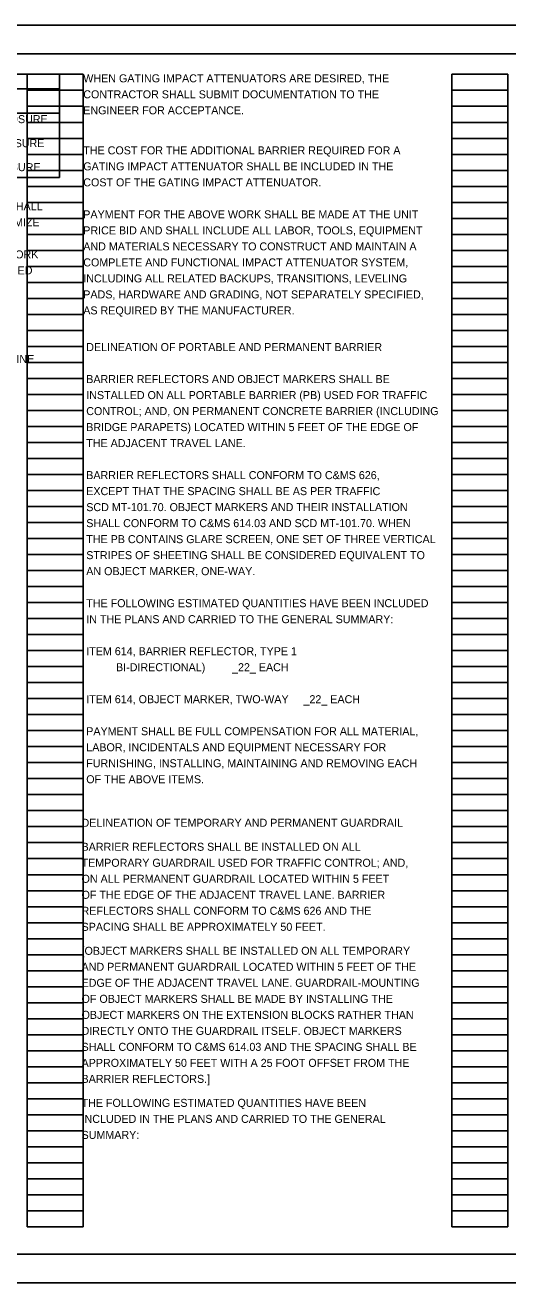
# Model space of a CAD drawing. Extents: x -59 to 65, y -13 to 46.
# Drawn here: x 16.22 to 24.66, y 0 to 22 of the extents above; entities that cross this region are included whole.
import ezdxf

# ---------------------------------------------------------------- set-up
doc = ezdxf.new("R2010")
doc.units = 0
for name, color, linetype in [('SH_Border', 7, 'Continuous'), ('SH_Cut_Line', 7, 'Continuous'), ('SH_Data', 7, 'Continuous'), ('SH_Text', 7, 'Continuous')]:
    doc.layers.add(name, color=color, linetype=linetype)

msp = doc.modelspace()

# ---------------------------------------------------------------- linework, layer by layer
at = {"layer": 'SH_Border'}
msp.add_lwpolyline([(1.5, 21.5), (33.5, 21.5), (33.5, 0.5), (1.5, 0.5)], close=True, dxfattribs=at)
at = {"layer": 'SH_Cut_Line'}
msp.add_lwpolyline([(0, 0), (34, 0), (34, 22), (0, 22)], close=True, dxfattribs=at)
at = {"layer": 'SH_Data'}
for p, q in [((16.26, 0.98), (16.26, 21.14)), ((16.26, 21.14), (17.24, 21.14)), ((17.24, 0.98), (17.24, 21.14)), ((23.68, 0.98), (23.68, 21.14)), ((23.68, 21.14), (24.66, 21.14)), ((24.66, 0.98), (24.66, 21.14)), ((16.26, 20.86), (17.24, 20.86)), ((23.68, 20.86), (24.66, 20.86)), ((16.26, 20.58), (17.24, 20.58)), ((23.68, 20.58), (24.66, 20.58)), ((16.26, 20.3), (17.24, 20.3)), ((23.68, 20.3), (24.66, 20.3)), ((16.26, 20.02), (17.24, 20.02)), ((23.68, 20.02), (24.66, 20.02)), ((16.26, 19.74), (17.24, 19.74)), ((23.68, 19.74), (24.66, 19.74)), ((16.26, 19.46), (17.24, 19.46)), ((23.68, 19.46), (24.66, 19.46)), ((16.26, 19.18), (17.24, 19.18)), ((23.68, 19.18), (24.66, 19.18)), ((16.26, 18.9), (17.24, 18.9)), ((23.68, 18.9), (24.66, 18.9)), ((16.26, 18.62), (17.24, 18.62)), ((23.68, 18.62), (24.66, 18.62)), ((16.26, 18.34), (17.24, 18.34)), ((23.68, 18.34), (24.66, 18.34)), ((16.26, 18.06), (17.24, 18.06)), ((23.68, 18.06), (24.66, 18.06)), ((16.26, 17.78), (17.24, 17.78)), ((23.68, 17.78), (24.66, 17.78)), ((16.26, 17.5), (17.24, 17.5)), ((23.68, 17.5), (24.66, 17.5)), ((16.26, 17.22), (17.24, 17.22)), ((23.68, 17.22), (24.66, 17.22)), ((16.26, 16.94), (17.24, 16.94)), ((23.68, 16.94), (24.66, 16.94)), ((16.26, 16.66), (17.24, 16.66)), ((23.68, 16.66), (24.66, 16.66)), ((16.26, 16.38), (17.24, 16.38)), ((23.68, 16.38), (24.66, 16.38)), ((16.26, 16.1), (17.24, 16.1)), ((23.68, 16.1), (24.66, 16.1)), ((16.26, 15.82), (17.24, 15.82)), ((23.68, 15.82), (24.66, 15.82)), ((16.26, 15.54), (17.24, 15.54)), ((23.68, 15.54), (24.66, 15.54)), ((16.26, 15.26), (17.24, 15.26)), ((23.68, 15.26), (24.66, 15.26)), ((16.26, 14.98), (17.24, 14.98)), ((23.68, 14.98), (24.66, 14.98)), ((16.26, 14.7), (17.24, 14.7)), ((23.68, 14.7), (24.66, 14.7)), ((16.26, 14.42), (17.24, 14.42)), ((23.68, 14.42), (24.66, 14.42)), ((16.26, 14.14), (17.24, 14.14)), ((23.68, 14.14), (24.66, 14.14)), ((16.26, 13.86), (17.24, 13.86)), ((23.68, 13.86), (24.66, 13.86)), ((16.26, 13.58), (17.24, 13.58)), ((23.68, 13.58), (24.66, 13.58)), ((16.26, 13.3), (17.24, 13.3)), ((23.68, 13.3), (24.66, 13.3)), ((16.26, 13.02), (17.24, 13.02)), ((23.68, 13.02), (24.66, 13.02)), ((16.26, 12.74), (17.24, 12.74)), ((23.68, 12.74), (24.66, 12.74)), ((16.26, 12.46), (17.24, 12.46)), ((23.68, 12.46), (24.66, 12.46)), ((16.26, 12.18), (17.24, 12.18)), ((23.68, 12.18), (24.66, 12.18)), ((16.26, 11.9), (17.24, 11.9)), ((23.68, 11.9), (24.66, 11.9)), ((16.26, 11.62), (17.24, 11.62)), ((23.68, 11.62), (24.66, 11.62)), ((16.26, 11.34), (17.24, 11.34)), ((23.68, 11.34), (24.66, 11.34)), ((16.26, 11.06), (17.24, 11.06)), ((23.68, 11.06), (24.66, 11.06)), ((16.26, 10.78), (17.24, 10.78)), ((23.68, 10.78), (24.66, 10.78)), ((16.26, 10.5), (17.24, 10.5)), ((23.68, 10.5), (24.66, 10.5)), ((16.26, 10.22), (17.24, 10.22)), ((23.68, 10.22), (24.66, 10.22)), ((16.26, 9.94), (17.24, 9.94)), ((23.68, 9.94), (24.66, 9.94)), ((16.26, 9.66), (17.24, 9.66)), ((23.68, 9.66), (24.66, 9.66)), ((16.26, 9.38), (17.24, 9.38)), ((23.68, 9.38), (24.66, 9.38)), ((16.26, 9.1), (17.24, 9.1)), ((23.68, 9.1), (24.66, 9.1)), ((16.26, 8.82), (17.24, 8.82)), ((23.68, 8.82), (24.66, 8.82)), ((16.26, 8.54), (17.24, 8.54)), ((23.68, 8.54), (24.66, 8.54)), ((16.26, 8.26), (17.24, 8.26)), ((23.68, 8.26), (24.66, 8.26)), ((16.26, 7.98), (17.24, 7.98)), ((23.68, 7.98), (24.66, 7.98)), ((16.26, 7.7), (17.24, 7.7)), ((23.68, 7.7), (24.66, 7.7)), ((16.26, 7.42), (17.24, 7.42)), ((23.68, 7.42), (24.66, 7.42)), ((16.26, 7.14), (17.24, 7.14)), ((23.68, 7.14), (24.66, 7.14)), ((16.26, 6.86), (17.24, 6.86)), ((23.68, 6.86), (24.66, 6.86)), ((16.26, 6.58), (17.24, 6.58)), ((23.68, 6.58), (24.66, 6.58)), ((16.26, 6.3), (17.24, 6.3)), ((23.68, 6.3), (24.66, 6.3)), ((16.26, 6.02), (17.24, 6.02)), ((23.68, 6.02), (24.66, 6.02)), ((16.26, 5.74), (17.24, 5.74)), ((23.68, 5.74), (24.66, 5.74)), ((16.26, 5.46), (17.24, 5.46)), ((23.68, 5.46), (24.66, 5.46)), ((16.26, 5.18), (17.24, 5.18)), ((23.68, 5.18), (24.66, 5.18)), ((16.26, 4.9), (17.24, 4.9)), ((23.68, 4.9), (24.66, 4.9)), ((16.26, 4.62), (17.24, 4.62)), ((23.68, 4.62), (24.66, 4.62)), ((16.26, 4.34), (17.24, 4.34)), ((23.68, 4.34), (24.66, 4.34)), ((16.26, 4.06), (17.24, 4.06)), ((23.68, 4.06), (24.66, 4.06)), ((16.26, 3.78), (17.24, 3.78)), ((23.68, 3.78), (24.66, 3.78)), ((16.26, 3.5), (17.24, 3.5)), ((23.68, 3.5), (24.66, 3.5)), ((16.26, 3.22), (17.24, 3.22)), ((23.68, 3.22), (24.66, 3.22)), ((16.26, 2.94), (17.24, 2.94)), ((23.68, 2.94), (24.66, 2.94)), ((16.26, 2.66), (17.24, 2.66)), ((23.68, 2.66), (24.66, 2.66)), ((16.26, 2.38), (17.24, 2.38)), ((23.68, 2.38), (24.66, 2.38)), ((16.26, 2.1), (17.24, 2.1)), ((23.68, 2.1), (24.66, 2.1)), ((16.26, 1.82), (17.24, 1.82)), ((23.68, 1.82), (24.66, 1.82)), ((16.26, 1.54), (17.24, 1.54)), ((23.68, 1.54), (24.66, 1.54)), ((16.26, 1.26), (17.24, 1.26)), ((23.68, 1.26), (24.66, 1.26)), ((16.26, 0.98), (17.24, 0.98)), ((23.68, 0.98), (24.66, 0.98))]:
    msp.add_line(p, q, dxfattribs=at)
at = {"layer": 'SH_Text'}
for p, q in [((16.825, 21.139), (16.825, 19.333)), ((9.82, 20.461), (16.825, 20.461)), ((9.82, 19.333), (16.825, 19.333))]:
    msp.add_line(p, q, dxfattribs=at)
msp.add_lwpolyline([(16.825, 20.888), (9.82, 20.888), (9.82, 21.14), (16.825, 21.14)], close=True, dxfattribs=at)

# ---------------------------------------------------------------- texts
for s, p in [('WHEN GATING IMPACT ATTENUATORS ARE DESIRED, THE', (17.24, 21)), ('CONTRACTOR SHALL SUBMIT DOCUMENTATION TO THE', (17.24, 20.72)), ('ENGINEER FOR ACCEPTANCE.', (17.24, 20.44)), ('>=2 WEEKS      14 CALENDAR DAYS PRIOR TO CLOSURE', (11.5, 20.286)), ('> 12 HOURS     7 CALENDAR DAYS  PRIOR TO CLOSURE', (11.5, 19.866)), ('THE COST FOR THE ADDITIONAL BARRIER REQUIRED FOR A', (17.24, 19.74)), ('<= 12 HOURS    2 BUSINESS DAYS PRIOR TO CLOSURE', (11.5, 19.446)), ('GATING IMPACT ATTENUATOR SHALL BE INCLUDED IN THE', (17.24, 19.46)), ('COST OF THE GATING IMPACT ATTENUATOR.', (17.24, 19.18)), ('LENGTH AND DURATION OF LANE CLOSURES AND RESTRICTIONS SHALL', (9.82, 18.76)), ('PAYMENT FOR THE ABOVE WORK SHALL BE MADE AT THE UNIT', (17.24, 18.62)), ('BE AT THE APPROVAL OF THE ENGINEER. IT IS THE INTENT TO MINIMIZE ', (9.82, 18.48)), ('PRICE BID AND SHALL INCLUDE ALL LABOR, TOOLS, EQUIPMENT', (17.24, 18.34)), ('RESTRICTIONS OVER SEGMENTS OF THE PROJECT IN WHICH NO WORK ', (9.82, 17.92)), ('AND MATERIALS NECESSARY TO CONSTRUCT AND MAINTAIN A', (17.24, 18.06)), ('COMPLETE AND FUNCTIONAL IMPACT ATTENUATOR SYSTEM,', (17.24, 17.78)), ('IS ANTICIPATED WITHIN A REASONABLE TIME FRAME, AS DETERMINED ', (9.82, 17.64)), ('INCLUDING ALL RELATED BACKUPS, TRANSITIONS, LEVELING', (17.24, 17.5)), ('PADS, HARDWARE AND GRADING, NOT SEPARATELY SPECIFIED,', (17.24, 17.22)), ('AS REQUIRED BY THE MANUFACTURER.', (17.24, 16.94)), ('DELINEATION OF PORTABLE AND PERMANENT BARRIER', (17.292, 16.299)), ('FORMAT AND THE NUMBER OF DAYS OF THE CLOSURE. THE LAST LINE ', (9.82, 16.091)), ('BARRIER REFLECTORS AND OBJECT MARKERS SHALL BE', (17.292, 15.739)), ('INSTALLED ON ALL PORTABLE BARRIER (PB) USED FOR TRAFFIC', (17.292, 15.459)), ('CONTROL; AND, ON PERMANENT CONCRETE BARRIER (INCLUDING', (17.292, 15.179)), ('BRIDGE PARAPETS) LOCATED WITHIN 5 FEET OF THE EDGE OF', (17.292, 14.899)), ('THE ADJACENT TRAVEL LANE.', (17.292, 14.619)), ('BARRIER REFLECTORS SHALL CONFORM TO C&MS 626,', (17.292, 14.059)), ('EXCEPT THAT THE SPACING SHALL BE AS PER TRAFFIC', (17.292, 13.779)), ('SCD MT-101.70. OBJECT MARKERS AND THEIR INSTALLATION', (17.292, 13.499)), ('SHALL CONFORM TO C&MS 614.03 AND SCD MT-101.70. WHEN', (17.292, 13.219)), ('THE PB CONTAINS GLARE SCREEN, ONE SET OF THREE VERTICAL', (17.292, 12.939)), ('STRIPES OF SHEETING SHALL BE CONSIDERED EQUIVALENT TO', (17.292, 12.659)), ('AN OBJECT MARKER, ONE-WAY.', (17.292, 12.379)), ('THE FOLLOWING ESTIMATED QUANTITIES HAVE BEEN INCLUDED', (17.292, 11.819)), ('IN THE PLANS AND CARRIED TO THE GENERAL SUMMARY:', (17.292, 11.539)), ('ITEM 614, BARRIER REFLECTOR, TYPE 1', (17.292, 10.979)), ('          BI-DIRECTIONAL)         _22_ EACH', (17.292, 10.699)), ('ITEM 614, OBJECT MARKER, TWO-WAY     _22_ EACH', (17.292, 10.139)), ('PAYMENT SHALL BE FULL COMPENSATION FOR ALL MATERIAL,', (17.292, 9.579)), ('LABOR, INCIDENTALS AND EQUIPMENT NECESSARY FOR', (17.292, 9.299)), ('FURNISHING, INSTALLING, MAINTAINING AND REMOVING EACH', (17.292, 9.019)), ('OF THE ABOVE ITEMS.', (17.292, 8.739)), ('DELINEATION OF TEMPORARY AND PERMANENT GUARDRAIL', (17.21, 7.978)), ('BARRIER REFLECTORS SHALL BE INSTALLED ON ALL', (17.21, 7.558)), ('TEMPORARY GUARDRAIL USED FOR TRAFFIC CONTROL; AND,', (17.21, 7.278)), ('ON ALL PERMANENT GUARDRAIL LOCATED WITHIN 5 FEET', (17.21, 6.998)), ('OF THE EDGE OF THE ADJACENT TRAVEL LANE. BARRIER', (17.21, 6.718)), ('REFLECTORS SHALL CONFORM TO C&MS 626 AND THE', (17.21, 6.438)), ('SPACING SHALL BE APPROXIMATELY 50 FEET.', (17.21, 6.158)), ('[OBJECT MARKERS SHALL BE INSTALLED ON ALL TEMPORARY', (17.21, 5.738)), ('AND PERMANENT GUARDRAIL LOCATED WITHIN 5 FEET OF THE', (17.21, 5.458)), ('EDGE OF THE ADJACENT TRAVEL LANE. GUARDRAIL-MOUNTING', (17.21, 5.178)), ('OF OBJECT MARKERS SHALL BE MADE BY INSTALLING THE', (17.21, 4.898)), ('OBJECT MARKERS ON THE EXTENSION BLOCKS RATHER THAN', (17.21, 4.618)), ('DIRECTLY ONTO THE GUARDRAIL ITSELF. OBJECT MARKERS', (17.21, 4.338)), ('SHALL CONFORM TO C&MS 614.03 AND THE SPACING SHALL BE', (17.21, 4.058)), ('APPROXIMATELY 50 FEET WITH A 25 FOOT OFFSET FROM THE', (17.21, 3.778)), ('BARRIER REFLECTORS.]', (17.21, 3.498)), ('THE FOLLOWING ESTIMATED QUANTITIES HAVE BEEN', (17.21, 3.078)), ('INCLUDED IN THE PLANS AND CARRIED TO THE GENERAL', (17.21, 2.798)), ('SUMMARY:', (17.21, 2.518))]:
    msp.add_text(s, height=0.14, dxfattribs=at).set_placement(p)

doc.saveas('drawing.dxf')
